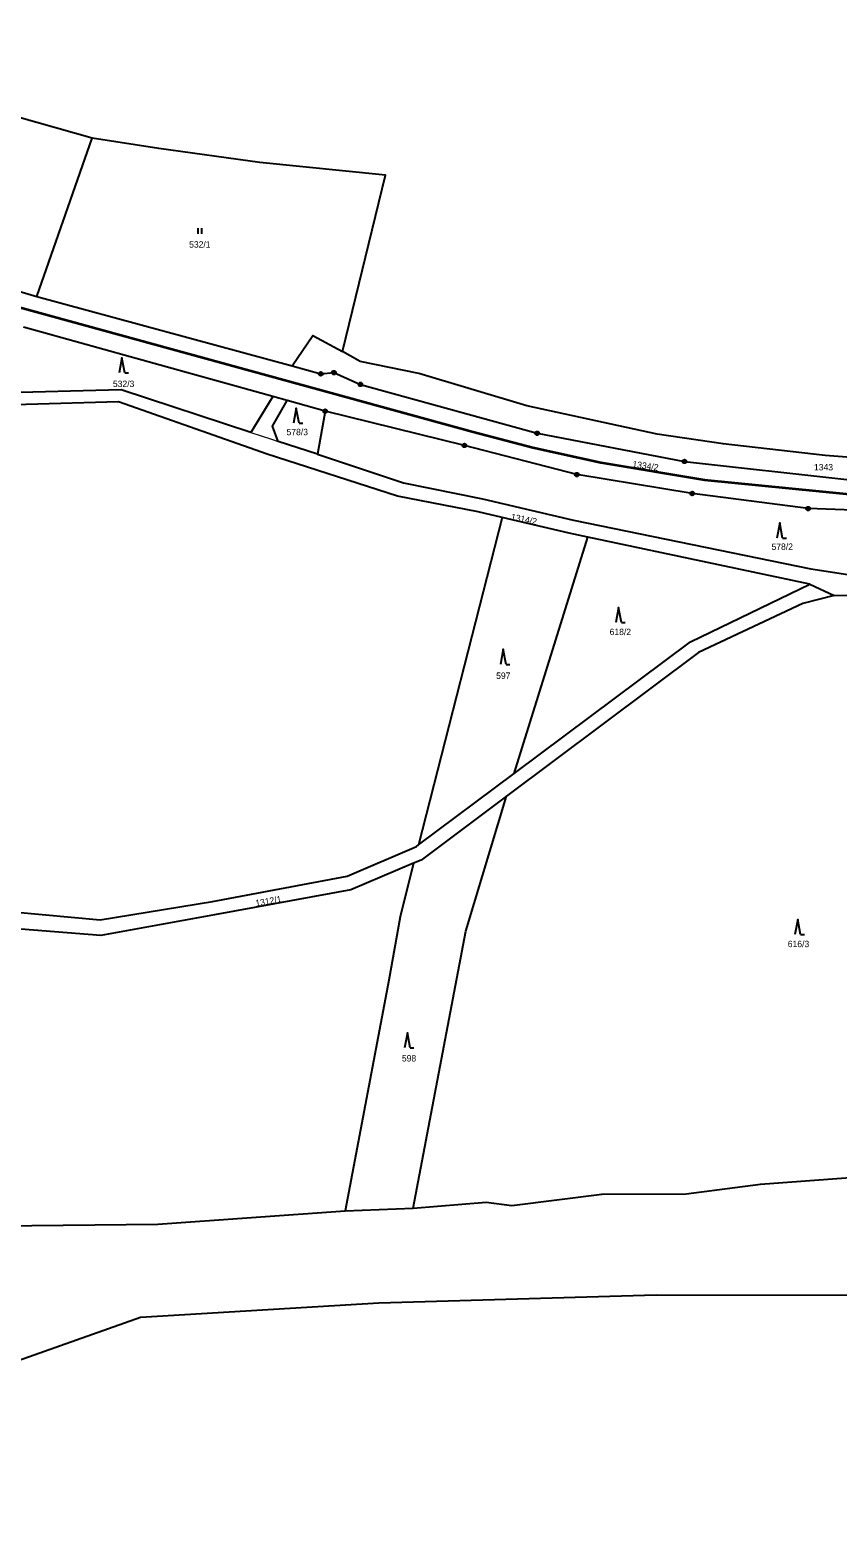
# Model space of a CAD drawing. Extents: x -872229 to -869198, y -1075981 to -1074329.
# Drawn here: x -869759.2 to -869544.8, y -1075719.7 to -1075319.4 of the extents above; entities that cross this region are included whole.
import ezdxf

# ---------------------------------------------------------------- set-up
doc = ezdxf.new("R2010")
doc.units = 0
doc.header["$LTSCALE"] = 0.68
for name, color, linetype, lineweight in [('1', 7, 'Continuous', 25), ('3', 7, 'Continuous', 25), ('4', 7, 'Continuous', 13), ('6', 7, 'Continuous', 25), ('8', 7, 'Continuous', 25)]:
    doc.layers.add(name, color=color, linetype=linetype, lineweight=lineweight)
doc.layers.add('2', color=7, linetype='Continuous')

msp = doc.modelspace()

# ---------------------------------------------------------------- linework, layer by layer
at = {"layer": '1'}
for p, q in [((-869757.47, -1075390.06), (-869689.66, -1075408.53)), ((-869694.77, -1075416.68), (-869760.99, -1075398.24)), ((-869689.66, -1075408.53), (-869682.1, -1075410.63)), ((-869680.93, -1075420.53), (-869690.98, -1075417.73)), ((-869682.99, -1075432.01), (-869693.4, -1075428.58)), ((-869552.3, -1075466.48), (-869611.2, -1075454.02)), ((-869552.3, -1075466.48), (-869545.81, -1075469.48)), ((-869656.72, -1075536.14), (-869656.16, -1075535.72))]:
    msp.add_line(p, q, dxfattribs=at)
for points in [[(-869742.8, -1075348.02), (-869767.51, -1075341.02), (-869775.27, -1075338.64), (-869785.4, -1075334.51), (-869794.46, -1075328.86), (-869803.48, -1075319.37), (-869813.74, -1075351.24), (-869816.07, -1075356.1), (-869821.67, -1075367.58)], [(-869821.67, -1075367.58), (-869823.79, -1075372.09), (-869775.47, -1075384.75), (-869757.47, -1075390.06), (-869742.8, -1075348.02)], [(-869676.3, -1075404.74), (-869664.95, -1075357.91), (-869698.26, -1075354.49), (-869725.06, -1075350.77), (-869742.8, -1075348.02)], [(-869689.66, -1075408.53), (-869684.2, -1075400.47), (-869676.3, -1075404.74)], [(-869470.63, -1075431.72), (-869482.67, -1075433.38), (-869492.77, -1075434.3), (-869516.25, -1075434.78), (-869548.16, -1075432.33), (-869575.31, -1075429.18), (-869592.79, -1075426.68), (-869627.42, -1075419.15), (-869656.02, -1075410.53), (-869671.66, -1075407.34), (-869676.3, -1075404.74)], [(-869633.9, -1075448.79), (-869640.35, -1075447.27), (-869661.71, -1075443.1), (-869696.29, -1075431.95), (-869735.78, -1075418.09), (-869784.91, -1075419.45), (-869829.22, -1075413.77), (-869837.88, -1075413.34), (-869849.23, -1075414.84), (-869864.5, -1075417.75), (-869881.67, -1075417.62), (-869942.3, -1075409.15)], [(-869682.1, -1075410.63), (-869678.59, -1075410.32), (-869671.56, -1075413.43), (-869624.66, -1075426.43), (-869585.55, -1075433.9), (-869542.43, -1075438.72), (-869516.5, -1075439.44), (-869471.65, -1075436.24), (-869470.63, -1075431.72)], [(-869693.4, -1075428.58), (-869694.91, -1075424.51), (-869690.98, -1075417.73), (-869694.77, -1075416.68), (-869700.66, -1075426.2), (-869735.08, -1075414.89), (-869768.68, -1075415.77)], [(-869474.41, -1075449.19), (-869490.49, -1075448.38), (-869521.65, -1075447.59), (-869552.7, -1075446.43), (-869583.47, -1075442.4), (-869614.13, -1075437.41), (-869643.97, -1075429.64), (-869680.93, -1075420.53), (-869682.99, -1075432.01), (-869660.1, -1075439.54)], [(-869660.1, -1075439.54), (-869639.17, -1075443.87), (-869615.03, -1075449.51), (-869552.02, -1075462.41), (-869529.57, -1075465.84), (-869493.81, -1075464.4), (-869478.29, -1075465.32)], [(-869633.9, -1075448.79), (-869656.16, -1075535.72), (-869630.72, -1075516.75), (-869611.2, -1075454.02)], [(-869611.2, -1075454.02), (-869616.15, -1075452.97), (-869633.9, -1075448.79)], [(-869545.81, -1075469.48), (-869554.14, -1075471.6), (-869581.84, -1075484.64), (-869632.77, -1075522.77)], [(-869630.72, -1075516.75), (-869583.91, -1075481.84), (-869552.3, -1075466.48)], [(-869545.81, -1075469.48), (-869530, -1075469.33), (-869493.67, -1075469.07), (-869478.21, -1075470.13)], [(-869657.56, -1075632.18), (-869643.6, -1075558.66), (-869632.77, -1075522.77)], [(-869632.77, -1075522.77), (-869655.47, -1075539.76), (-869657.44, -1075540.59)], [(-869889.5, -1075592.13), (-869867.84, -1075583.27), (-869849.28, -1075576.32), (-869795.03, -1075560.97), (-869771.51, -1075552.75), (-869740.67, -1075555.67), (-869710.85, -1075550.74), (-869675.12, -1075544), (-869656.72, -1075536.14)], [(-869657.44, -1075540.59), (-869674.12, -1075547.66), (-869710.28, -1075554.3), (-869740.46, -1075559.8), (-869770.69, -1075557.44), (-869794.04, -1075564.75), (-869848.43, -1075580.14), (-869866.49, -1075586.59), (-869887.81, -1075595.64), (-869900.72, -1075605.56)], [(-869657.44, -1075540.59), (-869661, -1075554.81), (-869664.03, -1075571.68), (-869675.65, -1075632.94), (-869657.56, -1075632.18)], [(-869657.56, -1075632.18), (-869638.2, -1075630.62), (-869631.37, -1075631.49), (-869607.48, -1075628.49), (-869585.13, -1075628.43), (-869565.34, -1075625.83), (-869510.48, -1075621.78), (-869497.7, -1075618.94), (-869485.54, -1075612.97), (-869477.1, -1075605.86)], [(-869895.39, -1075719.74), (-869729.92, -1075661.11), (-869666.68, -1075657.35), (-869593.09, -1075655.24), (-869520.45, -1075655.26), (-869463.49, -1075641.67), (-869392.24, -1075631.04), (-869390.16, -1075631.43)], [(-869767.28, -1075640.08), (-869767.22, -1075636.85), (-869725.35, -1075636.46), (-869675.65, -1075632.94)]]:
    msp.add_lwpolyline(points, dxfattribs=at)
at = {"layer": '3'}
for p, q in [((-869714.621, -1075373.44), (-869714.621, -1075371.94)), ((-869713.62, -1075373.44), (-869713.62, -1075371.94)), ((-869734.11, -1075410.39), (-869733.114, -1075410.39)), ((-869687.86, -1075423.72), (-869686.864, -1075423.72)), ((-869559.49, -1075454.24), (-869558.494, -1075454.24)), ((-869602.28, -1075476.66), (-869601.284, -1075476.66)), ((-869632.92, -1075487.78), (-869631.924, -1075487.78)), ((-869554.71, -1075559.56), (-869553.714, -1075559.56)), ((-869658.36, -1075589.66), (-869657.364, -1075589.66))]:
    msp.add_line(p, q, dxfattribs=at)
for points in [[(-869734.11, -1075410.39), (-869734.86, -1075406.39), (-869735.61, -1075410.39)], [(-869687.86, -1075423.72), (-869688.61, -1075419.72), (-869689.36, -1075423.72)], [(-869559.49, -1075454.24), (-869560.24, -1075450.24), (-869560.99, -1075454.24)], [(-869602.28, -1075476.66), (-869603.03, -1075472.66), (-869603.78, -1075476.66)], [(-869632.92, -1075487.78), (-869633.67, -1075483.78), (-869634.42, -1075487.78)], [(-869554.71, -1075559.56), (-869555.46, -1075555.56), (-869556.21, -1075559.56)], [(-869658.36, -1075589.66), (-869659.11, -1075585.66), (-869659.86, -1075589.66)]]:
    msp.add_lwpolyline(points, dxfattribs=at)
at = {"layer": '4'}
msp.add_lwpolyline([(-869700.66, -1075426.2), (-869695.14, -1075428.01), (-869693.4, -1075428.58)], dxfattribs=at)
at = {"layer": '6', "lineweight": 35}
msp.add_lwpolyline([(-869860.88, -1075365.74), (-869846.01, -1075369.94), (-869704.43, -1075408.78), (-869641.66, -1075426.07), (-869625.84, -1075430.18), (-869607.72, -1075434.15), (-869580.2, -1075438.82), (-869542.66, -1075442.5), (-869518.18, -1075443.57), (-869485.71, -1075443.04), (-869459.17, -1075441.98), (-869409.77, -1075437.63)], dxfattribs=at)
at = {"layer": '8'}
for centre, radius in [((-869678.59, -1075410.3199), 0.5), ((-869682.1, -1075410.6299), 0.5), ((-869682.1, -1075410.6299), 0.0303), ((-869678.59, -1075410.3199), 0.0303), ((-869671.56, -1075413.4299), 0.5), ((-869671.56, -1075413.4299), 0.0303), ((-869680.93, -1075420.5299), 0.5), ((-869680.93, -1075420.5299), 0.0303), ((-869643.97, -1075429.6399), 0.5), ((-869643.97, -1075429.6399), 0.0303), ((-869624.66, -1075426.4299), 0.5), ((-869624.66, -1075426.4299), 0.0303), ((-869585.55, -1075433.8999), 0.5), ((-869614.13, -1075437.4099), 0.5), ((-869614.13, -1075437.4099), 0.0303), ((-869585.55, -1075433.8999), 0.0303), ((-869583.47, -1075442.3999), 0.5), ((-869583.47, -1075442.3999), 0.0303), ((-869552.7, -1075446.4299), 0.5), ((-869552.7, -1075446.4299), 0.0303)]:
    msp.add_circle(centre, radius, dxfattribs=at)

# ---------------------------------------------------------------- texts
at = {"layer": '2'}
for s, p in [('532/1', (-869717.03, -1075377.12)), ('532/3', (-869737.27, -1075414.14)), ('578/3', (-869691.18, -1075426.94)), ('1343', (-869551.16, -1075436.28)), ('578/2', (-869562.44, -1075457.39)), ('618/2', (-869605.41, -1075480.01)), ('597', (-869635.53, -1075491.64)), ('616/3', (-869558.12, -1075562.88)), ('598', (-869660.55, -1075593.24))]:
    msp.add_text(s, height=1.7, dxfattribs=at).set_placement(p)
for s, rotation, p in [('1334/2', 352, (-869599.448, -1075435.411)), ('1314/2', 349, (-869631.722, -1075449.404)), ('1312/1', 10, (-869699.262, -1075552.087))]:
    msp.add_text(s, height=1.7, rotation=rotation, dxfattribs=at).set_placement(p)

doc.saveas('drawing.dxf')
